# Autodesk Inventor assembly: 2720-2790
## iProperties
Author: Administrator
Shininess: 64.0
Angle Display Precision: 2
Document Length Units: 11272
Document Angle Units: 11286
Document Time Units: 11279
Document Mass Units: 11290
Document Length Units Precision: 3
Document Angle Units Precision: 2
Compacted: False
PropertySet Name: _Private Model Information
Created: 2002-03
Part Number: 2720-2790
Document SubType Name: Assembly
Designer: Administrator
Control State: 0
Master: False
Checked Out: False
PropertySet Name: Design Tracking Control
Density: 0.0
Volumn: 0.0
Area: 0.0
PropertySet Name: Model Information
